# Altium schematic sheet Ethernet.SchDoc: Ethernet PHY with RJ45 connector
size A4; Date: Not used; ApprovedBy: Not used; CheckedBy: Not used; Author: Not used; CompanyName: STMicroelectronics; DrawnBy: Not used; Engineer: Not used; Organization: Not used; Address1: Not used; Address2: Not used; Address3: Not used; Address4: Not used; DocumentNumber: 6; Revision: Not used; SheetNumber: 6; SheetTotal: 9
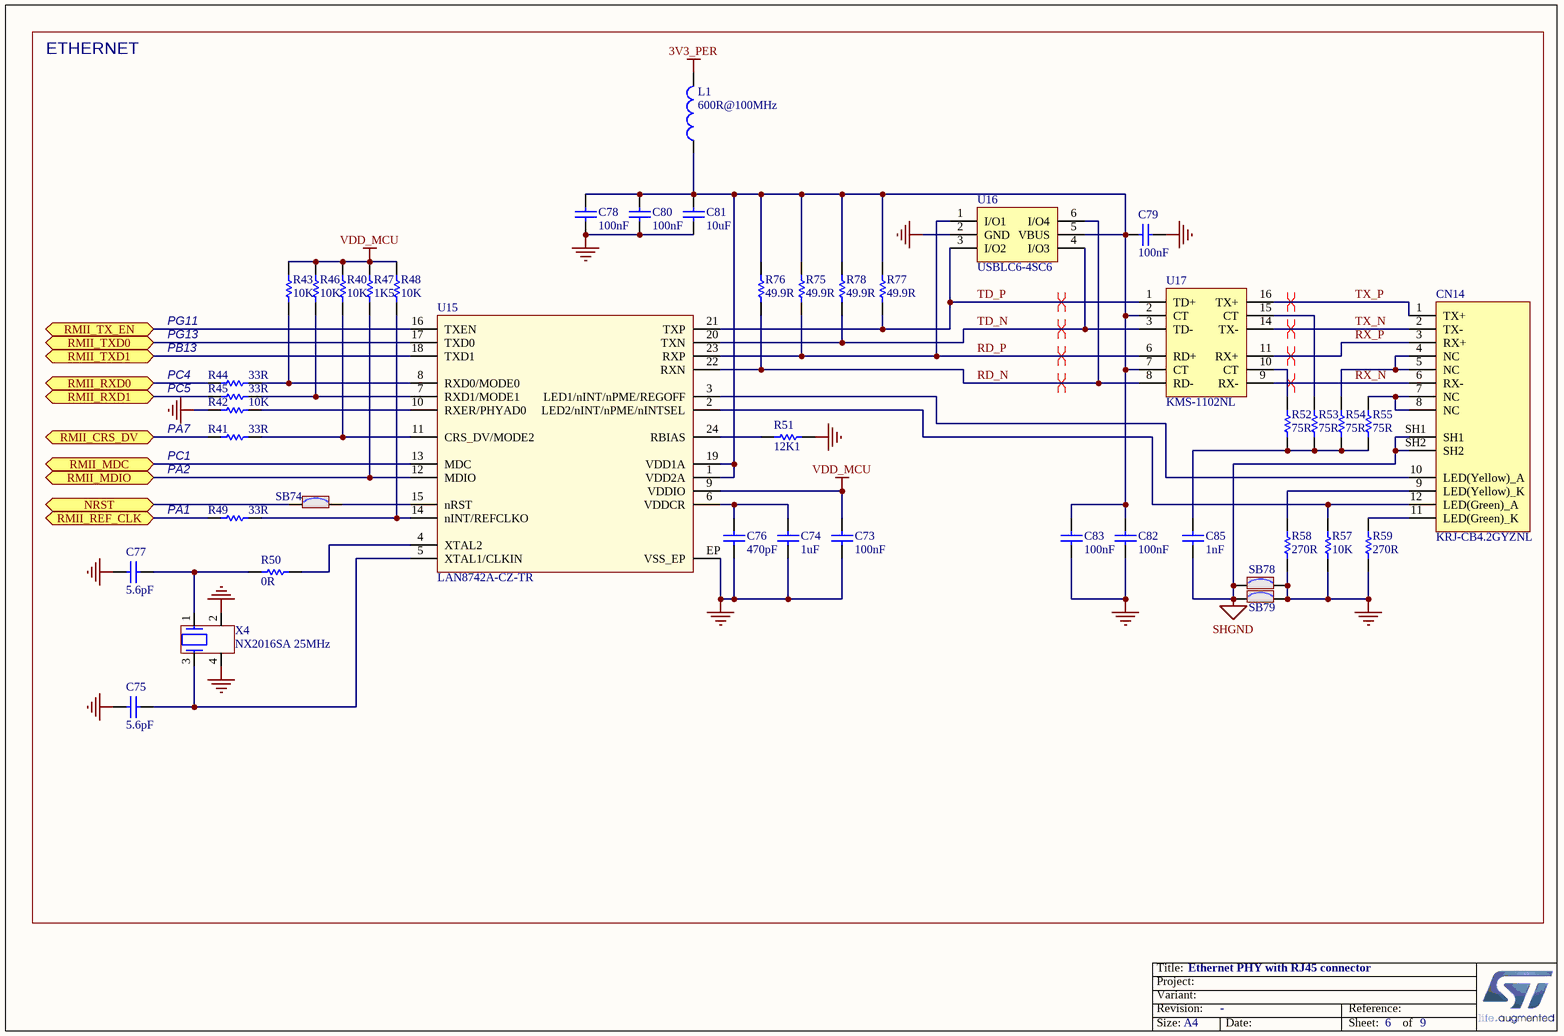
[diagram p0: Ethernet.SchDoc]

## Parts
C73  value 100nF  [C0603]  (hidden comment: Capacitor)
C74  value 1uF  [C0402]  (hidden comment: Capacitor)
C75  value 5.6pF  [C0402]  (hidden comment: Capacitor)
C76  value 470pF  [C0402]  (hidden comment: Capacitor)
C77  value 5.6pF  [C0402]  (hidden comment: Capacitor)
C78  value 100nF  [C0603]  (hidden comment: Capacitor)
C79  value 100nF  [C0603]  (hidden comment: Capacitor)
C80  value 100nF  [C0603]  (hidden comment: Capacitor)
C81  value 10uF  [C0603]  (hidden comment: Capacitor)
C82  value 100nF  [C0603]  (hidden comment: Capacitor)
C83  value 100nF  [C0603]  (hidden comment: Capacitor)
C85  value 1nF  [C1206_H1P6]  (hidden comment: Capacitor)
CN14  value KRJ-CB4.2GYZNL  [CON_RJ45_DGKYD_KRJ-CB4.2GYZNL]  (hidden comment: RJ45_KRJ-CB4.2GYZNL)
L1  value 600R@100MHz  [L0603]  (hidden comment: BEAD)
R40  value 10K  [R0402]  (hidden comment: Resistor)
R41  value 33R  [R0402]  (hidden comment: Resistor)
R42  value 10K  [R0402]  (hidden comment: Resistor)
R43  value 10K  [R0402]  (hidden comment: Resistor)
R44  value 33R  [R0402]  (hidden comment: Resistor)
R45  value 33R  [R0402]  (hidden comment: Resistor)
R46  value 10K  [R0402]  (hidden comment: Resistor)
R47  value 1K5  [R0402]  (hidden comment: Resistor)
R48  value 10K  [R0402]  (hidden comment: Resistor)
R49  value 33R  [R0402]  (hidden comment: Resistor)
R50  value 0R  [R0402]  (hidden comment: Resistor)
R51  value 12K1  [R0402]  (hidden comment: Resistor)
R52  value 75R  [R0402]  (hidden comment: Resistor)
R53  value 75R  [R0402]  (hidden comment: Resistor)
R54  value 75R  [R0402]  (hidden comment: Resistor)
R55  value 75R  [R0402]  (hidden comment: Resistor)
R57  value 10K  [R0402]  (hidden comment: Resistor)
R58  value 270R  [R0402]  (hidden comment: Resistor)
R59  value 270R  [R0402]  (hidden comment: Resistor)
R75  value 49.9R  [R0402]  (hidden comment: Resistor)
R76  value 49.9R  [R0402]  (hidden comment: Resistor)
R77  value 49.9R  [R0402]  (hidden comment: Resistor)
R78  value 49.9R  [R0402]  (hidden comment: Resistor)
SB74  SB_ON  [SOLDER-BRIDGE_R0603-0R]  (value not drawn)
SB78  SB_ON  [SOLDER-BRIDGE_R0603-0R]  (value not drawn)
SB79  SB_ON  [SOLDER-BRIDGE_R0603-0R]  (value not drawn)
U15  LAN8742A-CZ-TR  [ICC_VQFN24-EPAD_4X4_P050]
U16  USBLC6-4SC6  [ESD_SOT23-6L]
U17  KMS-1102NL  [TRS_DGKYD_KMS-1102NL]
X4  value NX2016SA 25MHz  [CRY_NX2016SA_4P]  (hidden comment: XTAL_4_PINS)

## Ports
NRST (bidir), RMII_CRS_DV (bidir), RMII_MDC (bidir), RMII_MDIO (bidir), RMII_REF_CLK (bidir), RMII_RXD0 (bidir), RMII_RXD1 (bidir), RMII_TX_EN (bidir), RMII_TXD0 (bidir), RMII_TXD1 (bidir)

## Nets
3V3_PER: L1.2
GND: C73.1 C74.1 C75.1 C76.1 C77.1 C78.1 C79.2 C80.1 C81.1 C82.1 C83.1 R42.2 R51.2 R57.1 R58.1 R59.1 SB78.2 SB79.2 U15.EP(VSS_EP) U16.2(GND) X4.2 X4.4
SHGND: C85.1 CN14.SH1 CN14.SH2 SB78.1 SB79.1
VDD_MCU: C73.2 R40.2 R43.2 R46.2 R47.2 R48.2 U15.9(VDDIO)
NRST: SB74.1 ; port NRST
RD_N: R76.1 U15.22(RXN) U16.6(I/O4) U17.8(RD-)
RD_P: R75.1 U15.23(RXP) U16.1(I/O1) U17.6(RD+)
RMII_CRS_DV: R41.1 ; port RMII_CRS_DV
RMII_MDC: U15.13(MDC) ; port RMII_MDC
RMII_MDIO: R47.1 U15.12(MDIO) ; port RMII_MDIO
RMII_REF_CLK: R49.1 ; port RMII_REF_CLK
RMII_RXD0: R44.1 ; port RMII_RXD0
RMII_RXD1: R45.1 ; port RMII_RXD1
RMII_TX_EN: U15.16(TXEN) ; port RMII_TX_EN
RMII_TXD0: U15.17(TXD0) ; port RMII_TXD0
RMII_TXD1: U15.18(TXD1) ; port RMII_TXD1
RX_N: CN14.6(RX-) U17.9(RX-)
RX_P: CN14.3(RX+) U17.11(RX+)
TD_N: R78.1 U15.20(TXN) U16.4(I/O3) U17.3(TD-)
TD_P: R77.1 U15.21(TXP) U16.3(I/O2) U17.1(TD+)
TX_N: CN14.2(TX-) U17.14(TX-)
TX_P: CN14.1(TX+) U17.16(TX+)
NetC74_2: C74.2 C76.2 U15.6(VDDCR)
NetC75_2: C75.2 U15.5(XTAL1/CLKIN) X4.3
NetC77_2: C77.2 R50.1 X4.1
NetC78_2: C78.2 C79.1 C80.2 C81.2 C82.2 C83.2 L1.1 R75.2 R76.2 R77.2 R78.2 U15.1(VDD2A) U15.19(VDD1A) U16.5(VBUS) U17.2(CT) U17.7(CT)
NetC85_2: C85.2 R52.1 R53.1 R54.1 R55.1
NetCN14_4: CN14.4(NC) CN14.5(NC) R54.2
NetCN14_7: CN14.7(NC) CN14.8(NC) R55.2
NetCN14_9: CN14.9(LED(Yellow)_K) R58.2
NetCN14_10: CN14.10(LED(Yellow)_A) U15.3(LED1/nINT/nPME/REGOFF)
NetCN14_11: CN14.11(LED(Green)_K) R59.2
NetCN14_12: CN14.12(LED(Green)_A) R57.2 U15.2(LED2/nINT/nPME/nINTSEL)
NetR40_1: R40.1 R41.2 U15.11(CRS_DV/MODE2)
NetR42_1: R42.1 U15.10(RXER/PHYAD0)
NetR43_1: R43.1 R44.2 U15.8(RXD0/MODE0)
NetR45_2: R45.2 R46.1 U15.7(RXD1/MODE1)
NetR48_1: R48.1 R49.2 U15.14(nINT/REFCLKO)
NetR50_2: R50.2 U15.4(XTAL2)
NetR51_1: R51.1 U15.24(RBIAS)
NetR52_2: R52.2 U17.10(CT)
NetR53_2: R53.2 U17.15(CT)
NetSB74_2: SB74.2 U15.15(nRST)

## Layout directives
differential pair: RD_N, RD_P, RX_N, RX_P, TD_N, TD_P, TX_N, TX_P

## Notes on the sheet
- ETHERNET
- PG11
- PG13
- PB13
- PC4
- PC5
- PA7
- PC1
- PA2
- (near R49) PA1

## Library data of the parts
C73 C78-C80 C82 C83 = MCD-00237: Capacitor, MLCC, 100nF, 6V3, X5R, 10%, 0603, T=0,8mm; Manufacturer_Part_Number: CC0603KRX5R5BB104; Manufacturer: YAGEO; Provided_By: SUBCO; ECCN_US: EAR99; ECCN_EU: NEC
C74 = MCD-00095: Capacitor, MLCC, 1uF, 6V3, X5R, 10%, 0402, T=0,5mm; Manufacturer_Part_Number: GRM155R61E105KA12; Manufacturer: MURATA; Alternate_Manufacturer_Part_Number: GRM155R60J105KE19; Provided_By: SUBCO; ECCN_US: EAR99; ECCN_EU: NEC
C75 C77 = MCD-01374: Capacitor, MLCC, 5.6pF, 50V, NPO, 5%, 0402, T=0,5mm; Manufacturer_Part_Number: CC0402BRNPO9BN5R6; Manufacturer: YAGEO; Provided_By: SUBCO
C76 = MCD-00724: Capacitor, MLCC, 470pF, 50V, NPO, 5%, 0402, T=0,5mm; Manufacturer_Part_Number: CC0402JRNPO9BN471; Manufacturer: YAGEO; Provided_By: SUBCO
C81 = MCD-01124: Capacitor, MLCC, 10µF, 10V, X5R, 10%, 0603, T=0.8mm; Manufacturer_Part_Number: GRM188R61A106KAAL; Manufacturer: MURATA; Provided_By: SUBCO; ECCN_US: EAR99; ECCN_EU: NEC
C85 = MCD-00722: Capacitor, MLCC, 1nF, 2KV, X7R, 10%, 1206, T=1,25mm; Manufacturer_Part_Number: CC1206KKX7RDBB102; Manufacturer: YAGEO; Provided_By: SUBCO
CN14 = MCD-00717: RJ45 jack, single port, with LEDS, Metal shielded dip low profile; Part_Type: Connector; Manufacturer: DONGGUAN KEYOUDA ELECTRONIC TECHNOLOGY; Provided_By: SUBCO
L1 = MCD-00047: SMD Chip ferrite bead, 600R@100MHz +/-25%, 350mA, 500mohm DC, 0603, T=0.8mm; Part_Type: Inductor; Manufacturer_Part_Number: FCM1608KF-601T03; Manufacturer: TAI-TECH; Provided_By: SUBCO
R40 R42 R43 R46 R48 R57 = MCD-00053: Resistor,10K,0402,1%,1/16W; Manufacturer_Part_Number: RC0402FR-0710KL; Manufacturer: YAGEO; Provided_By: SUBCO; ECCN_US: EAR99; ECCN_EU: NEC
R41 R44 R45 R49 = MCD-00455: Resistor,33R,0402,1%,1/16W; Manufacturer_Part_Number: RC0402FR-0733RL; Manufacturer: YAGEO; Provided_By: SUBCO; ECCN_US: EAR99; ECCN_EU: NEC
R47 = MCD-00068: Resistor,1K5,0402,1%,1/16W; Manufacturer_Part_Number: RC0402FR-071K5L; Manufacturer: YAGEO; Provided_By: SUBCO; ECCN_US: EAR99; ECCN_EU: NEC
R50 = MCD-00052: Resistor,0R,0402,5%,1/16W; Manufacturer_Part_Number: RC0402JR-070RL; Manufacturer: YAGEO; Provided_By: SUBCO; ECCN_US: EAR99; ECCN_EU: NEC
R51 = MCD-00723: Resistor,12K1,0402,1%,1/16W; Manufacturer_Part_Number: RC0402FR-0712K1L; Manufacturer: YAGEO; Provided_By: SUBCO; ECCN_US: EAR99; ECCN_EU: NEC
R52-R55 = MCD-00515: Resistor,75R,0402,1%,1/16W; Manufacturer_Part_Number: RC0402FR-0775RL; Manufacturer: YAGEO; Provided_By: SUBCO; ECCN_US: EAR99; ECCN_EU: NEC
R58 R59 = MCD-00441: Resistor,270R,0402,1%,1/16W; Manufacturer_Part_Number: RC0402FR-07270RL; Manufacturer: YAGEO; Provided_By: SUBCO; ECCN_US: EAR99; ECCN_EU: NEC
R75-R78 = MCD-00565: Resistor,49R9,0402,1%,1/16W; Manufacturer_Part_Number: RC0402FR-0749R9L; Manufacturer: YAGEO; Provided_By: SUBCO; ECCN_US: EAR99; ECCN_EU: NEC
SB74 SB78 SB79 = MCD-00071: Solder Bridge ON; Part_Type: Mechanical; Manufacturer_Part_Number: RC0603JR-070RL; Manufacturer: YAGEO; Provided_By: SUBCO
U15 = MCD-00719: 10/100M RMII Ethernet transceiver; Part_Type: IC; Manufacturer: MICROCHIP; Provided_By: SUBCO
U16 = MCD-00250: Very low capacitance ESD protection , 4 lines; Part_Type: IC; Manufacturer: STMICROELECTRONICS; BMS_Part_Number: 9151001; Provided_By: SUBCO with ST control; ECCN_US: EAR99; ECCN_EU: NEC
U17 = MCD-00718: Discrete Magnetic Transformer Module, 16 pins, SMT, 100 Base-TX; Part_Type: IC; Manufacturer: DONGGUAN KEYOUDA ELECTRONIC TECHNOLOGY; Provided_By: SUBCO
X4 = MCD-01364: Crystal 25MHz, 6pF, +-20ppm, 80ohms max, SMD; Part_Type: Crystal_Osc; Manufacturer_Part_Number: NX2016SA 25MHz EXS00A-CS11321; Manufacturer: NDK; BMS_Part_Number: 9157044; Provided_By: SUBCO; ECCN_US: EAR99; ECCN_EU: NEC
